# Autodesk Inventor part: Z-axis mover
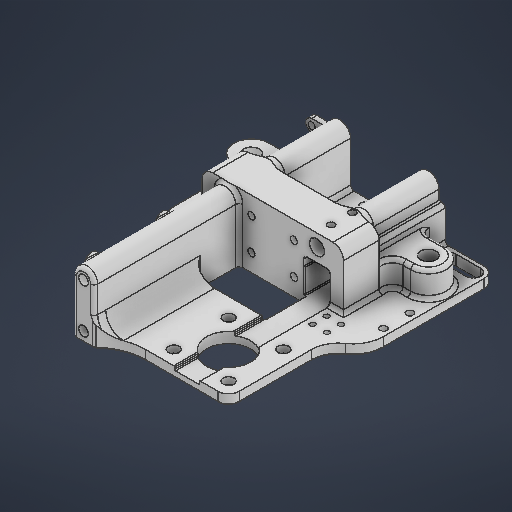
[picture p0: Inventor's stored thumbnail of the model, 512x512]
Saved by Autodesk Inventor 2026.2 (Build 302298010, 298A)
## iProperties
Created: 2026-04
Part Number: Z-axis mover
Material: 일반
Document SubType Name: Modeling
Designer: work
Density: 1 g/cm^3
Appearance: 기본값
Author: work
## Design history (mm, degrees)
sketch "스케치1"
  geometry: L1 (0, 0)-(8, 0); L2 (0, 0)-(0, 8); L3 (0, 0)-(-8, 0); L4 (0, 0)-(0, -8); L5 (0, 0)-(50, 0); L6 (0, 0)-(-50, 0); L7 (0, 0)-(0, 50); L8 (25, 0)-(25, -380); L9 (-25, 0)-(-25, -380); L10 (-25, 0)-(-25, 70); L11 (25, -380)-(-25, -380); L12 (25, 0)-(25, 0); L13 (25, 0)-(25, 120); L14 (-37.5, -395)-(37.5, -395); L15 (37.5, -395)-(37.5, -365); L16 (37.5, -365)-(-37.5, -365); L17 (-37.5, -365)-(-37.5, -395); L18 (-37.5, -395)-(37.5, -365); L19 (37.5, -395)-(-37.5, -365); L20 (-62.5, 38)-(62.5, 38); L21 (62.5, 38)-(62.5, -38); L22 (62.5, -38)-(-62.5, -38); L23 (-62.5, -38)-(-62.5, 38); L24 (-62.5, 38)-(62.5, -38); L25 (62.5, 38)-(-62.5, -38); L26 (62.5, -25)-(-62.5, -25); L27 (17, 38)-(-17, 38); L28 (-17, 38)-(-17, 61); L29 (-17, 61)-(17, 61); L30 (17, 61)-(17, 38); L31 (-22, 60.236)-(-22, 100); L32 (-22, 100)-(-28, 100); L33 (-28, 100)-(-28, -380); L34 (-28, -380)-(-22, -380); L35 (-22, -380)-(-22, 100); L36 (-40, 38)-(40, 38); L37 (40, 38)-(40, 18); L38 (40, 18)-(-40, 18); L39 (-40, 18)-(-40, 38); C1 r 5.25 at (0, 0); C2 r 11.3 at (0, 0); C3 r 2 at (8, 0); C4 r 2 at (0, 8); C5 r 2 at (-8, 0); C6 r 2 at (0, -8); C7 r 4.4 at (50, 0); C8 r 4.4 at (-50, 0); C9 r 4 at (0, 50); 7 further points
  constraints: 78 end point, 12 midpoint, 10 parallel, 9 centre point, 9 coincident, 8 horizontal, 6 perpendicular, 6 point on line, 5 vertical, 2 symmetric about line, 1 collinear, 22 other
  dimensions: "d0" = 10.5 diameter of C1; "d1" = 22.6 diameter of C2; "d2" = 8 distance of L1.start L1.end; "d3" = 4 diameter of C3; "d6" = 360 deg dimension on C1.centre L1.end (derived); "d8" = 50 distance of L4.start L5.end; "d9" = 8.8 diameter of C7; "d10" = 50 distance of L4.start L7.end; "d11" = 8 diameter of C9; "d12" = 12 distance of point (0, 38) L7.end; "d15" = 450 distance of L9.end L10.end; "d16" = 25 distance from line of point (0, 0) L8; "d17" = 25 distance from line of L10 C1.centre; "d19" = 500 distance of L8.end L13.end; "d20" = 120 vertical distance of point (0, 0) L13.end; "d21" = 75 distance between parallel lines of L17 L15; "d22" = 30 distance of L14.end L15.end; "d23" = 125 distance between parallel lines of L23 L21; "d24" = 25 distance from line of point (0, 0) L26; "d25" = 340 distance between parallel lines of L16 L26 (derived); "d26" = 34 distance of L28.end L29.end; "d27" = 23 distance of L27.end L28.end; "d30" = 6 distance between parallel lines of L33 L35; "d31" = 80 distance of L37.end L38.end; "d32" = 20 distance of L36.end L37.end; "d60" = 30 distance of L10.end point (-25, 100)
  node "스케치 - 원형 패턴1" dims "d6" = 360 deg (derived)
extrude "돌출1" new body sketch "스케치1" distance "d33" = 6; taper "d34" = 0 deg
extrude "돌출2" join sketch "스케치1" distance "d35" = 4; taper "d36" = 0 deg
extrude "돌출3" join sketch "스케치1" distance "d37" = 38; taper "d38" = 0 deg
sketch "스케치2"
  geometry: L1 (102.5, 6)-(22.5, 6) reference; L2 (87.5, 6)-(87.5, 31); L3 (93.5, 6)-(93.5, 31); L4 (81.5, 31)-(81.5, 6); L5 (0, 0)-(125, 0) reference; L6 (62.5, 6)-(37.5, 6); L7 (37.5, 6)-(37.5, 31); L8 (37.5, 31)-(62.5, 31); L9 (62.5, 31)-(62.5, 6); L10 (30.5, 4)-(44.5, 4); L11 (44.5, 4)-(44.5, 18); L12 (44.5, 18)-(30.5, 18); L13 (30.5, 18)-(30.5, 4); L14 (30.5, 4)-(44.5, 18); L15 (44.5, 4)-(30.5, 18); L16 (44.5, -10.5)-(86.5, -10.5); L17 (86.5, -10.5)-(86.5, 32.5); L18 (86.5, 32.5)-(44.5, 32.5); L19 (44.5, 32.5)-(44.5, -10.5); L20 (44.5, -10.5)-(86.5, 32.5); L21 (86.5, -10.5)-(44.5, 32.5); L22 (47.5, 32.5)-(47.5, -10.5); L23 (37.5, 6)-(37.5, 31); L24 (43.5, 6)-(43.5, 31); L25 (31.5, 31)-(31.5, 6); L26 (47, 1.5)-(28, 1.5); L27 (28, 1.5)-(28, 20.5); L28 (28, 20.5)-(47, 20.5); L29 (47, 20.5)-(47, 1.5); L30 (47, 1.5)-(28, 20.5); L31 (28, 1.5)-(47, 20.5); C1 r 2.75 at (87.5, 6); C2 r 2.75 at (87.5, 31); C3 r 4.25 at (37.5, 31); A1 r 6 centre (87.5, 6) between (81.5, 6) and (93.5, 6); A2 r 6 centre (87.5, 31) between (93.5, 31) and (81.5, 31); A3 r 6 centre (37.5, 6) between (31.5, 6) and (43.5, 6); A4 r 6 centre (37.5, 31) between (43.5, 31) and (31.5, 31); 16 further points
  constraints: 62 end point, 11 midpoint, 10 parallel, 10 tangent, 8 point on circle, 7 centre point, 7 perpendicular, 5 point on line, 4 horizontal, 2 coincident
  dimensions: "d39" = 5.5 diameter of C1; "d40" = 25 distance of L2.start L6.start; "d41" = 25 distance of L2.start L2.end; "d42" = 5.5 diameter of C2; "d43" = 25 distance of L7.end L8.end; "d44" = 25 distance of L6.end L7.end; "d45" = 8.5 diameter of C3; "d46" = 14 distance of L11.end L12.end; "d47" = 14 distance of L10.end L11.end; "d48" = 43 distance of L16.end L17.end; "d50" = 20 distance of L7.end point (37.5, 11); "d51" = 39 distance between parallel lines of L17 L22; "d52" = 3 distance between parallel lines of L22 L19; "d59" = 2.5 distance between parallel lines of L28 L12
extrude "돌출4" join sketch "스케치2" distance "d53" = 145; taper "d54" = 0 deg
extrude "돌출5" cut sketch "스케치2" extent not by distance; stored distance "d55" = 10; taper "d56" = 0 deg
sketch "스케치3"
  geometry: L1 (-31.5, 20.5)-(-31.5, 31) reference; L2 (-43.5, 31)-(-43.5, 20.5) reference; L3 (-30.5, 4)-(-44.5, 4) reference; L4 (-44.5, 18)-(-30.5, 18) reference; L5 (-28, 20.5)-(-31.5, 20.5) reference; L6 (-43.5, 20.5)-(-47, 20.5) reference; L7 (-47, 1.5)-(-41.469, 1.5) reference; L8 (-33.531, 1.5)-(-28, 1.5) reference; L9 (-28, 1.5)-(-28, 20.5) reference; L10 (-30.5, 18)-(-30.5, 4) reference; L11 (-44.5, 4)-(-44.5, 18) reference; L12 (-47, 20.5)-(-47, 1.5) reference; C1 r 6 at (-37.5, 31); A1 r 6 centre (-37.5, 6) between (-41.469, 1.5) and (-33.531, 1.5) reference; A2 r 6 centre (-37.5, 31) between (-31.5, 31) and (-43.5, 31) reference; 5 further points
  constraints: 1 centre point, 1 concentric
extrude "돌출6" cut sketch "스케치3" stored distance "d57" = 145; taper "d58" = 0 deg
sketch "스케치5"
  geometry: L1 (29.25, 38)-(20.75, 38) reference; L2 (18, 38)-(32, 38) reference; L3 (32, 38)-(18, 38) reference; L4 (-25, 38)-(62.5, 38) reference; L5 (40, 38)-(62.5, 38) reference; L6 (-40, 38)-(40, 38) reference; L7 (-62.5, 38)-(-40, 38) reference; L8 (-62.5, 38)-(-25, 38) reference; L9 (-25, 38)-(-31, 38) reference; L10 (-31, 38)-(-19, 38) reference; L11 (-19, 38)-(-25, 38) reference; L12 (25, 38)-(25, 88); L13 (9.5, 103.5)-(40.5, 103.5); L14 (40.5, 103.5)-(40.5, 72.5); L15 (40.5, 72.5)-(9.5, 72.5); L16 (9.5, 72.5)-(9.5, 103.5); L17 (9.5, 103.5)-(40.5, 72.5); L18 (40.5, 103.5)-(9.5, 72.5); L19 (1.5, 111.5)-(48.5, 111.5); L20 (48.5, 111.5)-(48.5, 64.5); L21 (48.5, 64.5)-(1.5, 64.5); L22 (1.5, 64.5)-(1.5, 111.5); L23 (1.5, 111.5)-(48.5, 64.5); L24 (48.5, 111.5)-(1.5, 64.5); L25 (-22.25, 120)-(-22.25, -25) reference; L26 (-31, 38)-(-19, 38) reference; L27 (-31, 38)-(-31, 120) reference; L28 (-19, 120)-(-31, 120) reference; L29 (-19, 38)-(-19, 120) reference; L30 (62.5, 38)-(62.5, -25) reference; L31 (40, 18)-(40, 38) reference; L32 (-62.5, 38)-(-25, 38) reference; L33 (-62.5, -25)-(-62.5, 38) reference; L34 (62.5, -25)-(-62.5, -25) reference; L35 (62.5, 38)-(62.5, -25) reference; L36 (-25, 38)-(62.5, 38) reference; L37 (-19, 38)-(19, 38); L38 (19, 38)-(19, 62); L39 (19, 62)-(-19, 62); L40 (-19, 62)-(-19, 38); L41 (-19, 38)-(-19, 120) reference; C1 r 12.5 at (25, 88); C2 r 2 at (9.5, 72.5); C3 r 2 at (40.5, 103.5); C4 r 2 at (9.5, 103.5); C5 r 2 at (40.5, 72.5); C6 r 2 at (0, -8) reference; C7 r 2 at (8, 0) reference; C8 r 2 at (0, 8) reference; C9 r 2 at (-8, 0) reference; C10 r 5.25 at (0, 0) reference; C11 r 4.4 at (50, 0) reference; C12 r 4.4 at (-50, 0) reference; A1 r 28.971 centre (1.5, 140.471) between (-19, 120) and (1.5, 111.5); A2 r 15 centre (63.5, 64.5) between (48.5, 64.5) and (55.046, 52.109); A3 r 17.08 centre (45.42, 38) between (62.5, 38) and (55.046, 52.109); 15 further points
  constraints: 34 end point, 8 centre point, 6 parallel, 6 point on circle, 5 coincident, 5 midpoint, 4 perpendicular, 4 tangent, 3 horizontal, 2 point on line, 5 other
  dimensions: "d61" = 25 distance from line of point (0, 38) L12; "d62" = 25 diameter of C1; "d63" = 31 distance of L14.end L15.end; "d64" = 31 distance of L13.end L14.end; "d65" = 4 diameter of C2; "d66" = 4 diameter of C3; "d67" = 4 diameter of C4; "d68" = 4 diameter of C5; "d69" = 50 distance of L12.start L12.end; "d70" = 8 distance between parallel lines of L14 L20; "d71" = 15 radius of A2; "d73" = 24 distance of L39.end L37.start
extrude "돌출7" join sketch "스케치5" distance "d74" = 6; taper "d75" = 0 deg
sketch "스케치6"
  geometry: L1 (-81.5, 31)-(-81.5, 0) reference; L2 (-81.5, 0)-(-43.5, 0) reference; L3 (-43.5, 0)-(-43.5, 4) reference; L4 (-30.5, 6)-(-22.5, 6) reference; L5 (-44.5, 18)-(-44.5, 4) reference; L6 (-30.5, 18)-(-44.5, 18) reference; L7 (-30.5, 6)-(-30.5, 18) reference; L8 (-22.5, 6)-(-22.5, 38) reference; L9 (-102.5, 38)-(-22.5, 38) reference; L10 (-102.5, 6)-(-102.5, 38) reference; L11 (-125, 6)-(-102.5, 6) reference; L12 (-125, 0)-(-125, 6) reference; L13 (-125, 0)-(-93.5, 0) reference; L14 (-93.5, 0)-(-93.5, 31) reference; L15 (-81.5, 6)-(-81.5, 31) reference; L16 (-93.5, 31)-(-93.5, 0) reference; L17 (0, 0)-(-125, 0) reference; L18 (-93.5, 6)-(-81.5, 6); L19 (-81.5, 6)-(-81.5, 0); L20 (-81.5, 0)-(-93.5, 0); L21 (-93.5, 0)-(-93.5, 6); L22 (-81.5, 0)-(-93.5, 0) reference; L23 (-81.5, 0)-(-81.5, 6) reference; L24 (-90.25, 6)-(-84.75, 6) reference; L25 (-44.5, 4)-(-43.5, 4) reference; C1 r 4.25 at (-37.5, 31) reference; C2 r 2.75 at (-87.5, 31) reference; A1 r 6 centre (-87.5, 31) between (-81.5, 31) and (-93.5, 31) reference; A2 r 6 centre (-87.5, 31) between (-81.5, 31) and (-93.5, 31) reference; A3 r 2.75 centre (-87.5, 6) between (-84.75, 6) and (-90.25, 6) reference; 10 further points
  constraints: 8 end point, 2 parallel, 2 point on line, 1 horizontal, 1 perpendicular
extrude "돌출8" join sketch "스케치6" stored distance "d76" = 6; taper "d77" = 0 deg
sketch "스케치7"
  geometry: L1 (47, 6)-(81.5, 6) reference; L2 (47, 20.5)-(43.5, 20.5) reference; L3 (43.5, 20.5)-(43.5, 31) reference; L4 (31.5, 31)-(31.5, 20.5) reference; L5 (31.5, 20.5)-(28, 20.5) reference; L6 (28, 20.5)-(28, 6) reference; L7 (0, 6)-(28, 6) reference; L8 (0, 0)-(0, 6) reference; L9 (0, 0)-(125, 0) reference; L10 (125, 0)-(125, 6) reference; L11 (93.5, 6)-(125, 6) reference; L12 (93.5, 6)-(93.5, 31) reference; L13 (81.5, 31)-(81.5, 6) reference; L14 (44.5, 18)-(44.5, 4) reference; L15 (44.5, 4)-(30.5, 4) reference; L16 (30.5, 4)-(30.5, 18) reference; L17 (30.5, 18)-(44.5, 18) reference; L18 (43.5, 4)-(30.5, 4) reference; L19 (43.5, 4)-(43.5, 6) reference; L20 (30.5, 6)-(43.5, 6) reference; L21 (30.5, 4)-(30.5, 6) reference; L22 (81.5, 0)-(43.5, 0) reference; L23 (81.5, 0)-(81.5, 6) reference; L24 (43.5, 6)-(81.5, 6) reference; L25 (43.5, 0)-(43.5, 6) reference; L26 (47, 6)-(47, 20.5) reference; C1 r 2.75 at (87.5, 31) reference; C2 r 2.75 at (87.5, 6) reference; C3 r 2.75 at (87.5, 31) reference; A1 r 6 centre (37.5, 31) between (43.5, 31) and (31.5, 31) reference; A2 r 6 centre (87.5, 31) between (93.5, 31) and (81.5, 31) reference; 4 further points
extrude "돌출9" cut sketch "스케치7" extent not by distance; stored distance "d78" = 0; taper "d79" = 0 deg
sketch "스케치8"
  geometry: L1 (50.5, 10)-(74.5, 10); L2 (74.5, 10)-(74.5, 28); L3 (74.5, 28)-(50.5, 28); L4 (50.5, 28)-(50.5, 10); L5 (50.5, 10)-(74.5, 28); L6 (74.5, 10)-(50.5, 28); L7 (102.5, 38)-(22.5, 38) reference; L8 (62.5, 38)-(62.5, 0); C1 r 2 at (50.5, 28); C2 r 2 at (50.5, 10); C3 r 2 at (74.5, 10); C4 r 2 at (74.5, 28); 1 further point
  constraints: 14 end point, 4 centre point, 4 coincident, 4 midpoint, 2 parallel, 1 horizontal, 1 perpendicular, 1 vertical
  dimensions: "d80" = 24 distance of L3.end L2.end; "d81" = 18 distance of L2.end L1.end; "d82" = 4 diameter of C1; "d83" = 4 diameter of C2; "d84" = 4 diameter of C3; "d85" = 4 diameter of C4
extrude "돌출10" cut sketch "스케치8" extent not by distance; stored distance "d86" = 18 (derived); taper "d87" = 0 deg
sketch "스케치9"
  geometry: L1 (59, -32)-(59, -7) reference; L2 (71, -7)-(71, -32) reference; L3 (80, -32)-(71, -32) reference; L4 (80, -32)-(80, 0) reference; L5 (0, 0)-(80, 0) reference; L6 (0, -32)-(0, 0) reference; L7 (5.5, -32)-(0, -32) reference; L8 (5.5, -32)-(5.5, -17.5) reference; L9 (5.5, -17.5)-(9, -17.5) reference; L10 (9, -17.5)-(9, -7) reference; L11 (21, -7)-(21, -17.5) reference; L12 (21, -17.5)-(24.5, -17.5) reference; L13 (59, -32)-(24.5, -32) reference; L14 (24.5, -17.5)-(24.5, -32) reference; C1 r 2 at (28, -28) reference; C2 r 2 at (52, -28) reference; C3 r 2 at (28, -10) reference; C4 r 2 at (52, -10) reference; C5 r 2 at (52, -28) reference; A1 r 6 centre (65, -7) between (71, -7) and (59, -7) reference; A2 r 6 centre (15, -7) between (21, -7) and (9, -7) reference; 5 further points
  constraints: 4 coincident
hole "구멍1" sketch "스케치9" at (52, -10), (28, -10), (28, -28), (52, -28) diameter "d88" = 4; stored, may be unused: countersink angle "d92" = 90 deg, drill point angle "d94" = 0 deg; dims "d89" = 6, "d90" = 6.2, "d91" = 4, "d93" = 8
sketch "스케치10"
  geometry: L1 (32, -98.356)-(32, -111.5) reference; L2 (32, -111.5)-(48.5, -111.5) reference; L3 (48.5, -111.5)-(48.5, -64.5) reference; L4 (62.5, -38)-(62.5, 25) reference; L5 (62.5, 25)-(34.5, 25) reference; L6 (34.5, 25)-(34.5, -18) reference; L7 (34.5, -18)-(40, -18) reference; L8 (40, -18)-(40, -38) reference; L9 (32, -38)-(40, -38) reference; L10 (32, -38)-(32, -77.644) reference; L11 (-31, -18)-(-31, 25) reference; L12 (-31, 25)-(-62.5, 25) reference; L13 (-62.5, 25)-(-62.5, -38) reference; L14 (-62.5, -38)-(-40, -38) reference; L15 (-40, -38)-(-40, -18) reference; L16 (-40, -18)-(-31, -18) reference; L17 (-50, -10)-(-31, -10); L18 (-50, 10)-(-31, 10); L19 (50, 10)-(34.5, 10); L20 (50, -10)-(34.5, -10); C1 r 4.4 at (50, 0) reference; C2 r 2 at (40.5, -72.5) reference; C3 r 2 at (40.5, -103.5) reference; C4 r 4.4 at (-50, 0) reference; A1 r 15 centre (63.5, -64.5) between (55.046, -52.109) and (48.5, -64.5) reference; A2 r 17.08 centre (45.42, -38) between (55.046, -52.109) and (62.5, -38) reference; A3 r 12.5 centre (25, -88) between (32, -98.356) and (32, -77.644) reference; A4 r 10 centre (-50, 0) between (-50, -10) and (-50, 10); A5 r 10 centre (50, 0) between (50, 10) and (50, -10); 1 further point
  constraints: 8 end point, 4 perpendicular, 4 point on circle, 4 point on line, 4 tangent, 2 centre point, 2 coincident
  dimensions: "d95" = 20 diameter of A4; "d96" = 20 diameter of A5
extrude "돌출11" join sketch "스케치10" stored distance "d97" = 10; taper "d98" = 0 deg
fillet "모깎기1" dims "d99" = 6
sketch "스케치11"
  geometry: C1 r 4.25 at (0, 0) reference; 1 further point
extrude "돌출12" cut sketch "스케치11" extent not by distance; stored distance "d100" = 0; taper "d101" = 0 deg
fillet "모깎기2" dims "d102" = 2
fillet "모깎기3" dims "d103" = 0.5
chamfer "모따기1" distance "d104" = 1; stored, may be unused: second distance "d105" = 2, angle "d106" = 45 deg
sketch "스케치12"
  geometry: L1 (17.5, -61.936)-(17.5, -78) reference; L2 (17, -62)-(-17, -62) reference; L3 (-19, -60)-(-19, -118) reference; L4 (-21, -120)-(-19.813, -120) reference; L5 (1.5, -111.5)-(17.5, -111.5) reference; L6 (17.5, -98)-(17.5, -111.5) reference; L7 (42, -40)-(42, -17.621) reference; L8 (32.5, -78)-(32.5, -40) reference; L9 (32.5, -111.5)-(32.5, -98) reference; L10 (32.5, -111.5)-(42.5, -111.5) reference; L11 (48.5, -105.5)-(48.5, -64.5) reference; L12 (62.5, -38)-(62.5, 19) reference; L13 (56.5, 25)-(36.5, 25) reference; L14 (36.5, 16)-(36.5, 25) reference; L15 (50, 12)-(40.5, 12) reference; L16 (45.657, -12)-(50, -12) reference; L17 (42, -40)-(42, -17.621) reference; L18 (32.5, -40)-(42, -40) reference; C1 r 2 at (9.5, -72.5) reference; C2 r 2 at (9.5, -103.5) reference; C3 r 2 at (40.5, -103.5) reference; C4 r 2 at (40.5, -72.5) reference; C5 r 2 at (40.5, -103.5) reference; A1 r 2 centre (17, -60) between (17, -62) and (17.5, -61.936) reference; A2 r 2 centre (-17, -60) between (-19, -60) and (-17, -62) reference; A3 r 2 centre (-21, -118) between (-21, -120) and (-19, -118) reference; A4 r 2 centre (-19.813, -118) between (-19.813, -120) and (-18.437, -119.451) reference; A5 r 28.971 centre (1.5, -140.471) between (1.5, -111.5) and (-18.437, -119.451) reference; A6 r 12.5 centre (25, -88) between (17.5, -78) and (17.5, -98) reference; A7 r 12.5 centre (25, -88) between (32.5, -98) and (32.5, -78) reference; A8 r 6 centre (42.5, -105.5) between (42.5, -111.5) and (48.5, -105.5) reference; A9 r 15 centre (63.5, -64.5) between (55.046, -52.109) and (48.5, -64.5) reference; A10 r 17.08 centre (45.42, -38) between (55.046, -52.109) and (62.5, -38) reference; A11 r 6 centre (56.5, 19) between (62.5, 19) and (56.5, 25) reference; A12 r 4 centre (40.5, 16) between (36.5, 16) and (40.5, 12) reference; A13 r 12 centre (50, 0) between (50, -12) and (50, 12) reference; A14 r 4 centre (45.657, -16) between (45.657, -12) and (42, -17.621) reference; 5 further points
  constraints: 4 coincident
hole "구멍2" sketch "스케치12" at (9.5, -103.5), (40.5, -103.5), (40.5, -72.5), (9.5, -72.5) diameter "d107" = 4; stored, may be unused: countersink angle "d111" = 90 deg, drill point angle "d113" = 0 deg; dims "d108" = 6, "d109" = 6.2, "d110" = 4, "d112" = 8
fillet "모깎기4" dims "d114" = 10
sketch "스케치13"
  geometry: L1 (78, -30)-(0, -30) reference; L2 (78, 0)-(78, -30) reference; L3 (0, 0)-(78, 0) reference; L4 (0, -30)-(0, 0) reference; L5 (68, 0)-(28, 0); L6 (28, 0)-(28, -25); L7 (28, -25)-(68, -25); L8 (68, -25)-(68, 0); C1 r 4 at (28, 0); C2 r 4 at (28, -25); C3 r 4 at (68, -25); C4 r 4 at (68, 0); 1 further point
  constraints: 8 end point, 4 centre point, 2 parallel, 1 coincident, 1 horizontal, 1 perpendicular, 1 point on line
  dimensions: "d115" = 40 distance of L7.end L6.end; "d116" = 25 distance of L6.end L5.end; "d117" = 10 distance between parallel lines of L2 L8; "d118" = 8 diameter of C1; "d119" = 8 diameter of C2; "d120" = 8 diameter of C3; "d121" = 8 diameter of C4
  node "투영된 루프17"
extrude "돌출13" join sketch "스케치13" stored distance "d122" = 8 (derived); taper "d123" = 0 deg
extrude "돌출14" join sketch "스케치13" distance "d124" = 1.5; taper "d125" = 0 deg
sketch "스케치14"
  geometry: L1 (4, 0)-(36, 0) reference; L2 (-28, 0)-(-4, 0) reference; L3 (-28, -30)-(-28, 0) reference; L4 (50, -30)-(-28, -30) reference; L5 (50, 0)-(50, -30) reference; L6 (44, 0)-(50, 0) reference; C1 r 4 at (40, -25) reference; C2 r 4 at (0, -25) reference; C3 r 2 at (0, 0); C4 r 2 at (0, -25); C5 r 2 at (40, -25); C6 r 2 at (40, 0); A1 r 4 centre (40, 0) between (36, 0) and (44, 0) reference; A2 r 4 centre (0, 0) between (-4, 0) and (4, 0) reference; 1 further point
  constraints: 4 centre point, 4 coincident
  dimensions: "d126" = 4 diameter of C3; "d127" = 4 diameter of C4; "d128" = 4 diameter of C5; "d129" = 4 diameter of C6
  node "투영된 루프18"
extrude "돌출15" cut sketch "스케치14" stored distance "d130" = 1.5; taper "d131" = 0 deg
extrude "돌출16" cut sketch "스케치14" stored distance "d132" = 10; taper "d133" = 0 deg
fillet "모깎기5" dims "d134" = 2
sketch "스케치15"
  geometry: L1 (-21.127, -38)-(34, -38) reference; L2 (25, -38)-(25, -18); C1 r 2 at (25, -18); C2 r 2 at (25, -30); 1 further point
  constraints: 2 centre point, 2 end point, 2 point on line, 1 coincident, 1 vertical
  dimensions: "d135" = 20 distance of L2.start L2.end; "d136" = 25 distance from line of L2 point (0, 0); "d137" = 4 diameter of C1; "d138" = 4 diameter of C2; "d139" = 12 distance of L2.end C2.centre
extrude "돌출17" cut sketch "스케치15" stored distance "d140" = 10; taper "d141" = 0 deg
sketch "스케치16" dims "d145" = 7
  geometry: L1 (13, -21.5)-(13, -1.9); L2 (8, -25)-(31.5, -25) reference; L3 (6, -23)-(6, 0) reference; L4 (13, -5.4)-(6, -5.4); L5 (13, 1.6)-(5.783, 1.6); L6 (13, -18)-(6, -18); L7 (-42.5, -26.5)-(-42.5, -13.5) reference; L8 (-56.5, -27.5)-(-43.5, -27.5) reference; L9 (-57.5, -13.5)-(-57.5, -26.5) reference; L10 (-43.5, -12.5)-(-56.5, -12.5) reference; L11 (31.5, -30)-(-81.5, -30) reference; L12 (31.5, -25)-(31.5, -30) reference; L13 (8, -25)-(31.5, -25) reference; L14 (6, -23)-(6, 0) reference; L15 (-6, 0)-(-6, -23) reference; L16 (-38.5, -25)-(-8, -25) reference; L17 (-40.5, -23)-(-40.5, -12.5) reference; L18 (-42.5, -10.5)-(-44, -10.5) reference; L19 (-44, -10.5)-(-44, 0) reference; L20 (-56, 0)-(-56, -10.5) reference; L21 (-56, -10.5)-(-57.5, -10.5) reference; L22 (-59.5, -12.5)-(-59.5, -23) reference; L23 (-81.5, -25)-(-61.5, -25) reference; L24 (-81.5, -30)-(-81.5, -25) reference; C1 r 2 at (13, -21.5); C2 r 2 at (13, -1.9); C3 r 4.25 at (-50, 0) reference; C4 r 2.75 at (0, 0) reference; C5 r 2.75 at (0, -25) reference; A1 r 3.5 centre (13, -1.9) between (13, -5.4) and (13, 1.6); A2 r 6 centre (0, 0) between (6, 0) and (-6, 0) reference; A3 r 1 centre (-43.5, -13.5) between (-42.5, -13.5) and (-43.5, -12.5) reference; A4 r 1 centre (-43.5, -26.5) between (-43.5, -27.5) and (-42.5, -26.5) reference; A5 r 1 centre (-56.5, -26.5) between (-57.5, -26.5) and (-56.5, -27.5) reference; A6 r 1 centre (-56.5, -13.5) between (-56.5, -12.5) and (-57.5, -13.5) reference; A7 r 2 centre (8, -23) between (6, -23) and (8, -25) reference; A8 r 6 centre (0, 0) between (6, 0) and (-6, 0) reference; A9 r 2 centre (-8, -23) between (-8, -25) and (-6, -23) reference; A10 r 2 centre (-38.5, -23) between (-40.5, -23) and (-38.5, -25) reference; A11 r 2 centre (-42.5, -12.5) between (-40.5, -12.5) and (-42.5, -10.5) reference; A12 r 6 centre (-50, 0) between (-44, 0) and (-56, 0) reference; A13 r 2 centre (-57.5, -12.5) between (-57.5, -10.5) and (-59.5, -12.5) reference; A14 r 2 centre (-61.5, -23) between (-61.5, -25) and (-59.5, -23) reference; 5 further points
  constraints: 8 end point, 4 point on line, 3 centre point, 3 coincident, 3 perpendicular, 3 point on circle, 2 horizontal, 1 tangent, 1 vertical, 3 other
  dimensions: "d142" = 4 diameter of C1; "d143" = 4 diameter of C2; "d144" = 7 diameter of A1; "d146" = 19.6 distance of L1.start L1.end; "d147" = 7 distance from line of L3 L1.start
extrude "돌출18" join sketch "스케치16" distance "d148" = 3; taper "d149" = 0 deg
fillet "모깎기6" dims "d150" = 1
sketch "스케치17"
  geometry: L1 (0, 0)-(0, 25); L2 (13.5, 25)-(-17, 25) reference; L3 (7.5, 21)-(-7.5, 21); L4 (58.5, -34)-(58.5, -19); L5 (62.5, -38)-(62.5, 19) reference; C1 r 2 at (-7.5, 21); C2 r 2 at (7.5, 21); C3 r 2 at (58.5, -34); C4 r 2 at (58.5, -19); 1 further point
  constraints: 6 end point, 4 centre point, 4 coincident, 2 point on line, 2 vertical, 1 horizontal, 1 midpoint
  dimensions: "d151" = 15 distance of L3.start L3.end; "d152" = 4 diameter of C1; "d153" = 4 diameter of C2; "d154" = 4 distance between parallel lines of L2 L3; "d155" = 15 distance of L4.start L4.end; "d156" = 4 diameter of C3; "d157" = 4 diameter of C4; "d158" = 4 distance between parallel lines of L5 L4; "d159" = 4 horizontal distance of L5.start L4.start
extrude "돌출19" cut sketch "스케치17" extent not by distance; stored distance "d160" = 0; taper "d161" = 0 deg
sketch "스케치18"
  geometry: L1 (-42, -17.621)-(-42, -38) reference; L2 (-50, -12)-(-45.657, -12) reference; C1 r 16 at (-60, -30); 1 further point
  constraints: 1 centre point
  dimensions: "d162" = 32 diameter of C1; "d163" = 2 distance edge to line of C1 L1; "d164" = 2 distance edge to line of C1 L2
extrude "돌출20" cut sketch "스케치18" distance "d165" = 2; taper "d166" = 0 deg
sketch "스케치19"
  geometry: L1 (56.5, 19)-(42.5, 19); L2 (56.5, 23)-(42.5, 23); L3 (42.5, 15)-(56.5, 15); L4 (36.5, 16)-(36.5, 25) reference; L5 (-56.5, 19)-(-48, 19); L6 (-56.5, 15)-(-48, 15); L7 (-48, 23)-(-56.5, 23); L8 (-46.144, -38)-(-42, -38) reference; L9 (-42, -17.621)-(-42, -38) reference; L10 (-50, -12)-(-45.657, -12) reference; L11 (-37, 12)-(-50, 12) reference; L12 (-33, 21)-(-33, 16) reference; L13 (-41.742, 21)-(-33, 21) reference; L14 (-41.742, 25)-(-56.5, 25) reference; L15 (-62.5, 19)-(-62.5, -14.197) reference; L16 (36.5, -52)-(44.5, -52); L17 (44.5, -52)-(44.5, -44); L18 (44.5, -44)-(36.5, -44); L19 (36.5, -44)-(36.5, -52); L20 (32.5, -40)-(42, -40) reference; L21 (32.5, -78)-(32.5, -40) reference; L22 (13.5, 25)-(13.5, -16.011) reference; L23 (13.5, 25)-(-17, 25) reference; L24 (-17, -12)-(-17, 25) reference; L25 (9.631, -16)-(-9.631, -16) reference; L26 (32.5, -78)-(32.5, -40) reference; L27 (32.5, -111.5)-(32.5, -98) reference; L28 (32.5, -111.5)-(42.5, -111.5) reference; L29 (48.5, -105.5)-(48.5, -64.5) reference; L30 (62.5, -38)-(62.5, 19) reference; L31 (56.5, 25)-(36.5, 25) reference; L32 (36.5, 16)-(36.5, 25) reference; L33 (50, 12)-(40.5, 12) reference; L34 (45.657, -12)-(50, -12) reference; L35 (42, -40)-(42, -17.621) reference; L36 (32.5, -40)-(42, -40) reference; L37 (-41.742, 25)-(-41.742, 21) reference; C1 r 1.5 at (36.5, -52); C2 r 1.5 at (36.5, -44); C3 r 1.5 at (44.5, -44); C4 r 1.5 at (44.5, -52); A1 r 4 centre (56.5, 19) between (56.5, 15) and (56.5, 23); A2 r 4 centre (42.5, 19) between (42.5, 23) and (42.5, 15); A3 r 6 centre (56.5, 19) between (62.5, 19) and (56.5, 25) reference; A4 r 4 centre (-56.5, 19) between (-56.5, 23) and (-56.5, 15); A5 r 4 centre (-48, 19) between (-48, 15) and (-48, 23); A6 r 6 centre (-56.5, 19) between (-56.5, 25) and (-62.5, 19) reference; A7 r 16 centre (-60, -30) between (-46.144, -38) and (-62.5, -14.197) reference; A8 r 4 centre (-45.657, -16) between (-42, -17.621) and (-45.657, -12) reference; A9 r 12 centre (-50, 0) between (-50, 12) and (-50, -12) reference; A10 r 4 centre (-37, 16) between (-37, 12) and (-33, 16) reference; A11 r 6 centre (-56.5, 19) between (-56.5, 25) and (-62.5, 19) reference; A12 r 4 centre (-13, -12) between (-17, -12) and (-13.912, -15.895) reference; A13 r 12.5 centre (25, -88) between (32.5, -98) and (32.5, -78) reference; A14 r 6 centre (42.5, -105.5) between (42.5, -111.5) and (48.5, -105.5) reference; A15 r 15 centre (63.5, -64.5) between (55.046, -52.109) and (48.5, -64.5) reference; A16 r 17.08 centre (45.42, -38) between (55.046, -52.109) and (62.5, -38) reference; A17 r 6 centre (56.5, 19) between (62.5, 19) and (56.5, 25) reference; A18 r 4 centre (40.5, 16) between (36.5, 16) and (40.5, 12) reference; A19 r 12 centre (50, 0) between (50, -12) and (50, 12) reference; A20 r 4 centre (45.657, -16) between (45.657, -12) and (42, -17.621) reference; 8 further points
  constraints: 24 end point, 10 point on circle, 8 centre point, 8 tangent, 4 coincident, 4 parallel, 3 horizontal, 3 midpoint, 2 concentric, 1 perpendicular, 4 other
  dimensions: "d167" = 8 diameter of A2; "d168" = 2 distance from line of point (38.5, 19) L4; "d169" = 8 diameter of A5; "d171" = 3 diameter of C1; "d172" = 3 diameter of C2; "d173" = 3 diameter of C3; "d174" = 3 diameter of C4; "d175" = 8 distance of L16.end L17.end; "d176" = 8 distance of L17.end L18.end; "d177" = 4 distance between parallel lines of L20 L18; "d178" = 4 distance from line of L21 point (36.5, -48)
extrude "돌출21" cut sketch "스케치19" extent not by distance; stored distance "d179" = 0; taper "d180" = 0 deg
sketch "스케치20"
  geometry: 1 further point
sketch "스케치21"
  geometry: L1 (7.5, -26.5)-(7.5, -13.5) reference; L2 (-6.5, -27.5)-(6.5, -27.5) reference; L3 (-7.5, -13.5)-(-7.5, -26.5) reference; L4 (6.5, -12.5)-(-6.5, -12.5) reference; L5 (81.5, -30)-(-31.5, -30) reference; L6 (81.5, -25)-(81.5, -30) reference; L7 (66.742, -25)-(81.5, -25) reference; L8 (63, -18)-(57, -18) reference; L9 (56, -17)-(56, -6.4) reference; L10 (57, -5.4)-(63, -5.4) reference; L11 (63, 1.6)-(56.499, 1.6) reference; L12 (44, 0)-(44, -23) reference; L13 (11.5, -25)-(42, -25) reference; L14 (9.5, -23)-(9.5, -12.5) reference; L15 (7.5, -10.5)-(6, -10.5) reference; L16 (6, -10.5)-(6, 0) reference; L17 (-6, 0)-(-6, -10.5) reference; L18 (-6, -10.5)-(-7.5, -10.5) reference; L19 (-9.5, -12.5)-(-9.5, -23) reference; L20 (-31.5, -25)-(-11.5, -25) reference; L21 (-31.5, -30)-(-31.5, -25) reference; L22 (-9.5, -12.5)-(-9.5, -7.5); L23 (-7.5, -5.5)-(7.5, -5.5); L24 (9.5, -12.5)-(9.5, -7.5); L25 (7.5, -13.5)-(7.5, -7.5); L26 (7.5, -7.5)-(-7.5, -7.5); L27 (-7.5, -7.5)-(-7.5, -13.5); L28 (-9.5, -13.5)-(9.5, -13.5); C1 r 2 at (63, -1.9) reference; C2 r 2 at (63, -21.5) reference; C3 r 4.25 at (0, 0) reference; C4 r 2.75 at (50, 0) reference; C5 r 2.75 at (50, -25) reference; A1 r 1 centre (6.5, -13.5) between (7.5, -13.5) and (6.5, -12.5) reference; A2 r 1 centre (6.5, -26.5) between (6.5, -27.5) and (7.5, -26.5) reference; A3 r 1 centre (-6.5, -26.5) between (-7.5, -26.5) and (-6.5, -27.5) reference; A4 r 1 centre (-6.5, -13.5) between (-6.5, -12.5) and (-7.5, -13.5) reference; A5 r 1 centre (66.742, -24) between (65.91, -23.444) and (66.742, -25) reference; A6 r 3.5 centre (63, -21.5) between (65.91, -23.444) and (63, -18) reference; A7 r 1 centre (57, -17) between (56, -17) and (57, -18) reference; A8 r 1 centre (57, -6.4) between (57, -5.4) and (56, -6.4) reference; A9 r 3.5 centre (63, -1.9) between (63, -5.4) and (63, 1.6) reference; A10 r 1 centre (56.499, 2.6) between (55.571, 2.229) and (56.499, 1.6) reference; A11 r 6 centre (50, 0) between (55.571, 2.229) and (44, 0) reference; A12 r 2 centre (42, -23) between (42, -25) and (44, -23) reference; A13 r 2 centre (11.5, -23) between (9.5, -23) and (11.5, -25) reference; A14 r 2 centre (7.5, -12.5) between (9.5, -12.5) and (7.5, -10.5) reference; A15 r 6 centre (0, 0) between (6, 0) and (-6, 0) reference; A16 r 2 centre (-7.5, -12.5) between (-7.5, -10.5) and (-9.5, -12.5) reference; A17 r 2 centre (-11.5, -23) between (-11.5, -25) and (-9.5, -23) reference; A18 r 2 centre (-7.5, -7.5) between (-7.5, -5.5) and (-9.5, -7.5); A19 r 2 centre (7.5, -7.5) between (9.5, -7.5) and (7.5, -5.5); A20 r 2 centre (-5.5, -9.5) between (-5.5, -7.5) and (-7.5, -9.5); A21 r 2 centre (5.5, -9.5) between (7.5, -9.5) and (5.5, -7.5); 8 further points
  constraints: 14 end point, 8 point on circle, 8 tangent, 6 point on line, 4 centre point, 2 vertical, 1 horizontal, 1 midpoint, 1 perpendicular, 12 other
  dimensions: "d181" = 7 distance from line of L4 point (0, -5.5); "d182" = 2 radius of A19; "d183" = 2 radius of A18; "d184" = 2 radius of A20; "d185" = 2 radius of A21; "d186" = 1 distance between parallel lines of L4 L28
  node "투영된 루프21"
extrude "돌출22" join sketch "스케치21" stored distance "d187" = 10; taper "d188" = 0 deg
extrude "돌출23" cut sketch "스케치21" extent not by distance; stored distance "d189" = 10; taper "d190" = 0 deg
chamfer "모따기2" distance "d191" = 0.5; stored, may be unused: second distance "d192" = 2, angle "d193" = 45 deg
node "솔리드1"
node "투영된 루프1"
node "투영된 루프2"
node "투영된 루프3"
node "투영된 루프4"
node "투영된 루프5"
node "투영된 루프6"
node "투영된 루프7"
node "투영된 루프8"
node "투영된 루프9"
node "투영된 루프10"
node "투영된 루프11"
node "투영된 루프12"
node "투영된 루프13"
node "투영된 루프14"
node "투영된 루프15"
node "투영된 루프16"
node "투영된 루프19"
node "투영된 루프20"
feature "A9D066F2-1C7D-4E18-AEED-F7BC21143FA4" dims "d88" = 4, "d89" = 6, "d90" = 6.2, "d91" = 4, "d92" = 90 deg, "d93" = 8, "d94" = 0
